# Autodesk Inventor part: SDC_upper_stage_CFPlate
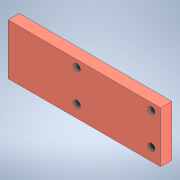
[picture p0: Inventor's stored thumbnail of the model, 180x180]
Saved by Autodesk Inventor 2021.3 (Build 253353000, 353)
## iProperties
Created: 2022-01
Part Number: SDC_upper_stage_CFPlate
Material: 一般
Document SubType Name: Modeling
Designer: kengo
Density: 1 g/cm^3
Appearance: 既定
Author: kengo
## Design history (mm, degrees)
sketch "スケッチ1"
  geometry: L1 (-82.081, 31.784)-(52.919, 31.784); L2 (52.919, 31.784)-(52.919, -13.216); L3 (52.919, -13.216)-(-82.081, -13.216); L4 (-82.081, -13.216)-(-82.081, 31.784); 1 further point
  constraints: 8 end point, 2 parallel, 1 horizontal, 1 perpendicular
  dimensions: "d0" = 135 distance of L1.start L1.end; "d1" = 45 distance of L1.end L2.end
extrude "押し出し1" new body sketch "スケッチ1" distance "d2" = 10; taper "d3" = 0 deg
sketch "スケッチ2"
  geometry: L1 (52.919, -13.216)-(52.919, 31.784) reference; L2 (-82.081, -13.216)-(52.919, -13.216) reference; 5 further points
  constraints: 1 horizontal, 1 vertical, 3 other
  dimensions: "d4" = 8 distance from line of L1 point (44.919, -2.216); "d5" = 11 distance from line of L2 point (44.919, -2.216); "d8" = 66 distance of point (44.919, -2.216) point (-21.081, -2.216); "d11" = 28 distance of point (44.919, -2.216) point (44.919, 25.784)
hole "穴1" sketch "スケッチ2" at (44.919, -2.216), (-21.081, -2.216), (44.919, 25.784), (-21.081, 25.784) diameter "d14" = 6; stored, may be unused: countersink angle "d18" = 90 deg, drill point angle "d20" = 118 deg; dims "d15" = 12, "d16" = 4, "d17" = 2, "d19" = 22.2
node "ソリッド1"
